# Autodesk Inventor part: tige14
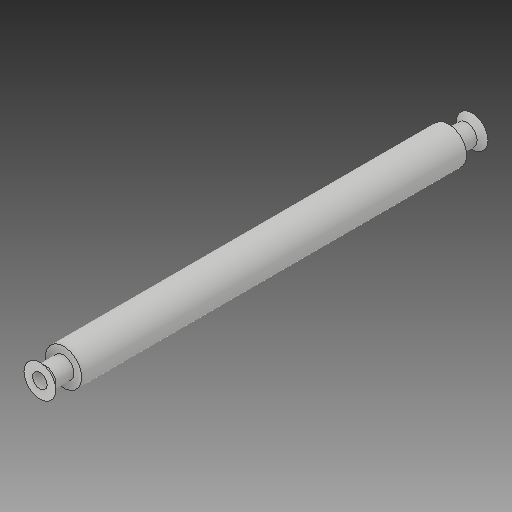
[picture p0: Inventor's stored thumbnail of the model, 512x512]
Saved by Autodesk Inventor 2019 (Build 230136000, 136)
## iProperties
Created: 2000-02
Part Number: tige14
Material: Générique
Document SubType Name: Modeling
Designer: si-nd67
Density: 1 g/cm^3
Appearance: Par défaut
Mass: 8.61516 g
Surface Area: 39.3555 cm^2
Volume: 8.61516 cm^3
Sending System: SolidWorks 2014
Last Author: tjost
Last Saved: 2019-02-07
Author: si-nd67
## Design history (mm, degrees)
feature "Symétrie2"
node "Solide1"
